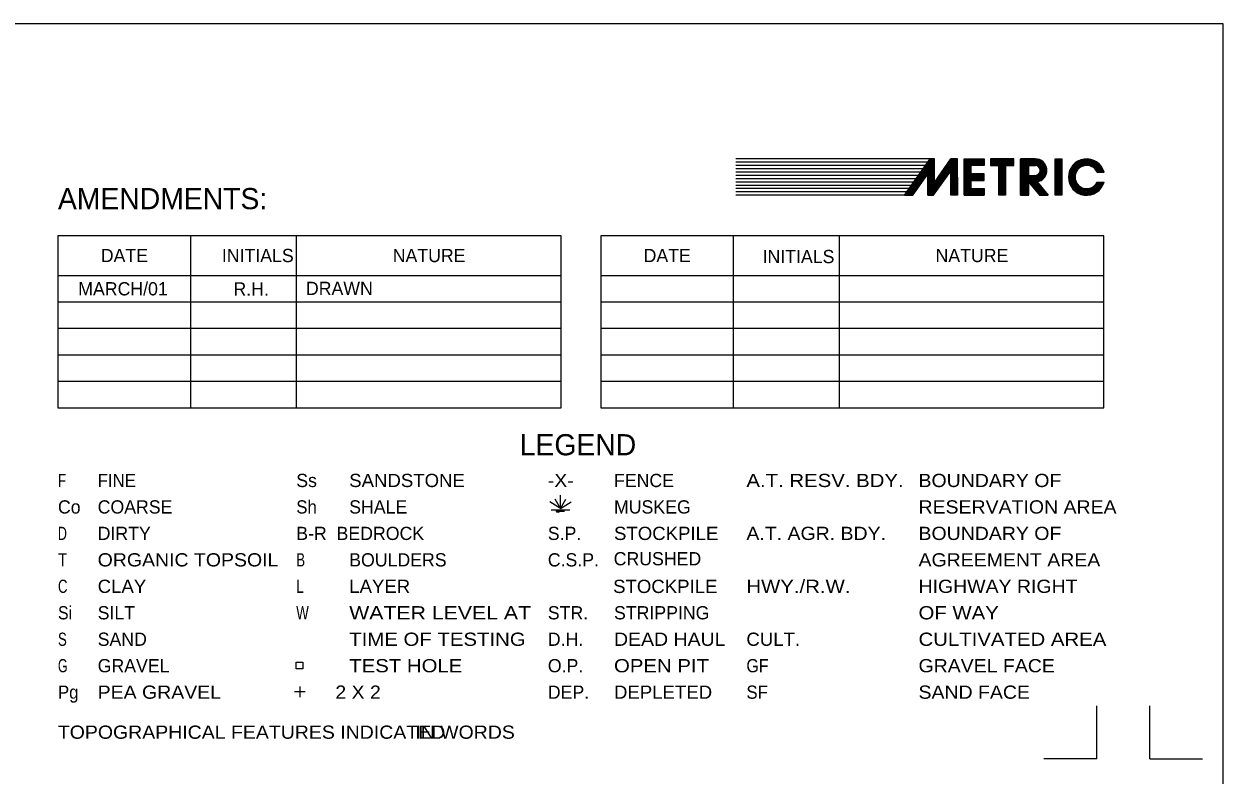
# Model space of a CAD drawing. Extents: x -496 to 480, y -452 to 700.
# Drawn here: x -2.8 to 450, y 416.2 to 700 of the extents above; entities that cross this region are included whole.
import ezdxf
from ezdxf.enums import TextEntityAlignment as Align

# ---------------------------------------------------------------- set-up
doc = ezdxf.new("R2010")
doc.units = 0
doc.header["$LTSCALE"] = 2
doc.header["$PDMODE"] = 32
doc.header["$PDSIZE"] = 1
doc.layers.add('3', color=7, linetype='Continuous', lineweight=13)

msp = doc.modelspace()

# ---------------------------------------------------------------- linework, layer by layer
at = {"layer": '3'}
for p, q in [((339.376, 648.989), (265.976, 648.989)), ((338.501, 647.739), (265.976, 647.739)), ((329.726, 635.239), (339.376, 648.989)), ((340.976, 640.064), (347.226, 648.989)), ((349.726, 648.989), (347.226, 648.989)), ((349.726, 635.239), (349.726, 648.989)), ((362.226, 648.989), (362.226, 646.489)), ((379.026, 648.989), (373.476, 648.989)), ((337.626, 646.489), (265.976, 646.489)), ((336.751, 645.239), (265.976, 645.239)), ((335.876, 643.989), (265.976, 643.989)), ((332.776, 635.239), (338.476, 643.364)), ((338.476, 635.239), (338.476, 643.389)), ((340.676, 635.264), (347.226, 644.614)), ((347.226, 635.239), (347.226, 644.614)), ((354.726, 646.489), (354.726, 643.364)), ((362.226, 646.489), (365.351, 646.489)), ((367.851, 646.489), (370.976, 646.489)), ((376.601, 646.489), (379.151, 646.489)), ((376.601, 642.739), (376.601, 646.489)), ((402.426, 643.989), (405.076, 643.989)), ((335.001, 642.739), (265.976, 642.739)), ((334.126, 641.489), (265.976, 641.489)), ((333.251, 640.239), (265.976, 640.239)), ((332.376, 638.989), (265.976, 638.989)), ((354.726, 640.864), (354.726, 637.739)), ((376.601, 642.739), (379.151, 642.739)), ((376.601, 640.239), (380.726, 635.239)), ((376.601, 635.239), (376.601, 640.239)), ((379.801, 640.289), (383.951, 635.239)), ((402.426, 640.239), (405.101, 640.239)), ((331.501, 637.739), (265.976, 637.739)), ((330.626, 636.489), (265.976, 636.489)), ((329.726, 635.239), (265.976, 635.239)), ((329.726, 635.239), (332.776, 635.239)), ((338.476, 635.239), (340.676, 635.239)), ((349.726, 635.239), (347.226, 635.239)), ((352.226, 635.239), (359.726, 635.239)), ((380.726, 635.239), (383.951, 635.239)), ((199.983, 619.973), (9.983, 619.973)), ((9.983, 619.973), (9.983, 554.973)), ((59.983, 619.973), (59.983, 554.973)), ((99.983, 619.973), (99.983, 554.973)), ((199.983, 554.973), (199.983, 619.973)), ((404.983, 619.973), (214.983, 619.973)), ((214.983, 619.973), (214.983, 554.973)), ((264.983, 619.973), (264.983, 554.973)), ((304.983, 619.973), (304.983, 554.973)), ((404.983, 554.973), (404.983, 619.973)), ((9.983, 604.973), (199.983, 604.973)), ((214.983, 604.973), (404.983, 604.973)), ((9.983, 594.973), (199.983, 594.973)), ((214.983, 594.973), (404.983, 594.973)), ((9.983, 584.973), (199.983, 584.973)), ((214.983, 584.973), (404.983, 584.973)), ((9.983, 574.973), (199.983, 574.973)), ((214.983, 574.973), (404.983, 574.973)), ((9.983, 564.973), (199.983, 564.973)), ((214.983, 564.973), (404.983, 564.973)), ((214.983, 554.973), (404.983, 554.973)), ((199.76, 516.875), (199.76, 521.875)), ((199.76, 516.875), (195.76, 519.375)), ((196.26, 516.375), (203.26, 516.375)), ((199.76, 516.875), (197.76, 520.375)), ((199.76, 516.875), (201.76, 520.375)), ((199.76, 516.875), (203.76, 519.375)), ((198.26, 515.875), (201.26, 515.875)), ((101.291, 449.597), (101.291, 445.597)), ((103.353, 447.618), (99.353, 447.618)), ((402.281, 422.339), (402.281, 442.339)), ((422.281, 422.339), (422.281, 442.339)), ((402.281, 422.339), (382.281, 422.339)), ((422.281, 422.339), (442.281, 422.339))]:
    msp.add_line(p, q, dxfattribs=at)
for points in [[(449.983, -450.027), (449.983, 399.973), (449.983, 699.973), (-450.017, 699.973), (-450.017, 49.973), (-450.017, -450.027)], [(329.901, 635.339), (339.401, 648.889), (340.901, 648.889), (340.901, 639.839), (347.251, 648.839), (349.626, 648.889), (349.676, 635.339), (347.351, 635.314), (347.301, 644.789), (340.576, 635.339), (338.576, 635.314), (338.576, 643.539), (332.701, 635.339), (330.076, 635.314), (339.501, 648.739), (340.801, 648.739), (340.776, 639.664), (347.276, 648.664), (349.526, 648.739), (349.651, 635.564), (347.501, 635.464), (347.426, 644.989), (340.526, 635.489), (338.726, 635.439), (338.676, 643.764), (332.651, 635.464), (330.301, 635.439), (339.576, 648.539), (340.651, 648.564), (340.651, 639.489), (347.351, 648.489), (349.301, 648.564), (349.476, 635.739), (347.726, 635.639), (347.626, 645.314), (340.451, 635.714), (338.926, 635.639), (338.876, 644.139), (332.501, 635.689), (330.701, 635.639)], [(330.701, 635.639), (339.651, 648.239), (340.326, 648.264), (340.476, 639.239), (347.526, 648.239), (349.126, 648.289), (349.226, 635.939), (348.001, 635.939), (347.851, 645.664), (340.326, 635.989), (339.151, 635.864), (339.126, 644.464), (332.401, 635.939), (331.076, 635.839), (339.651, 647.914), (340.151, 647.914), (340.251, 638.889), (347.601, 647.964), (348.926, 648.014), (349.026, 636.164), (348.251, 636.139), (348.051, 646.014), (340.226, 636.239), (339.351, 636.089), (339.326, 644.789), (332.226, 636.164), (331.476, 636.064), (339.701, 647.664), (339.926, 647.689), (340.126, 638.764), (347.751, 647.839), (348.701, 647.739), (348.826, 636.364), (348.476, 636.364), (348.176, 646.314), (340.126, 636.464), (339.551, 636.339), (339.426, 645.114), (332.201, 636.339), (331.851, 636.289)], [(331.851, 636.289), (339.701, 647.264), (339.926, 638.564), (347.826, 647.614), (348.451, 647.589), (348.701, 636.589), (348.251, 646.639), (340.126, 636.689), (339.726, 636.589), (339.576, 645.539), (332.301, 636.639), (339.526, 646.714), (339.576, 645.814), (335.101, 640.239), (339.401, 646.164), (339.401, 645.914), (338.176, 644.289)], [(340.976, 640.039), (340.976, 648.989), (339.376, 648.989)], [(352.226, 635.239), (352.226, 648.989), (359.726, 648.989)], [(352.376, 648.914), (359.651, 648.864), (359.676, 646.614), (354.626, 646.589), (354.626, 643.289), (359.651, 643.289), (359.651, 640.989), (354.651, 640.939), (354.626, 637.614), (359.676, 637.639), (359.651, 635.339), (352.351, 635.314), (352.376, 648.789), (359.551, 648.739), (359.551, 646.764), (354.501, 646.714), (354.501, 643.214), (359.551, 643.164), (359.551, 641.114), (354.551, 641.064), (354.526, 637.439), (359.551, 637.514), (359.501, 635.439), (352.501, 635.439), (352.576, 648.639), (359.401, 648.564), (359.426, 646.914), (354.376, 646.839), (354.351, 643.064), (359.426, 643.039), (359.376, 641.289), (354.401, 641.239), (354.376, 637.239), (359.401, 637.339), (359.376, 635.589), (352.701, 635.614), (352.726, 648.439), (359.226, 648.414), (359.251, 647.064), (354.251, 647.039)], [(354.251, 647.039), (354.176, 642.864), (359.251, 642.864), (359.176, 641.439), (354.251, 641.389), (354.201, 637.064), (359.201, 637.114), (359.176, 635.739), (352.926, 635.814), (352.976, 648.214), (359.026, 648.239), (359.076, 647.289), (354.076, 647.214), (354.001, 642.689), (359.051, 642.664), (359.026, 641.639), (354.076, 641.564), (354.026, 636.864), (359.051, 636.939), (359.026, 635.989), (353.126, 636.039), (353.226, 647.989), (358.801, 648.039), (358.826, 647.464), (353.926, 647.389), (353.851, 642.489), (358.876, 642.539), (358.801, 641.814), (353.951, 641.689), (353.851, 636.714), (358.901, 636.764), (358.901, 636.214), (353.351, 636.214), (353.476, 647.714), (358.601, 647.889), (358.626, 647.639), (353.776, 647.514), (353.751, 642.364), (358.626, 642.389), (358.601, 642.014)], [(358.601, 642.014), (353.826, 641.864), (353.726, 636.564), (358.701, 636.639), (358.701, 636.389), (353.551, 636.439), (353.626, 641.989), (358.376, 642.164), (358.326, 642.289), (353.576, 642.264), (353.676, 647.564)], [(359.726, 648.989), (359.726, 646.489), (354.726, 646.489)], [(370.976, 646.489), (370.976, 648.989), (362.226, 648.989)], [(362.351, 648.864), (370.851, 648.889), (370.851, 646.639), (367.701, 646.639), (367.751, 635.414), (365.451, 635.314), (365.451, 646.564), (362.351, 646.589), (362.351, 648.764), (370.801, 648.789), (370.726, 646.789), (367.601, 646.764), (367.676, 635.539), (365.576, 635.414), (365.626, 646.739), (362.476, 646.739), (362.476, 648.639), (370.626, 648.639), (370.576, 646.989), (367.426, 646.864), (367.526, 635.739), (365.751, 635.614), (365.776, 646.864), (362.701, 646.939), (362.726, 648.439), (370.451, 648.489), (370.376, 647.114), (367.276, 646.989), (367.376, 635.914), (365.901, 635.789), (365.951, 647.064), (362.901, 647.114), (362.901, 648.264), (370.201, 648.289), (370.201, 647.364), (367.076, 647.189), (367.226, 636.114), (366.126, 635.989), (366.101, 647.264), (363.101, 647.314)], [(363.101, 647.314), (363.151, 648.089), (369.976, 648.164), (369.926, 647.489), (366.876, 647.364), (367.026, 636.339), (366.351, 636.239), (366.276, 647.439), (363.326, 647.514), (363.401, 647.939), (369.751, 648.039), (369.701, 647.714), (366.726, 647.539), (366.851, 636.564), (366.476, 636.489), (366.426, 647.664), (363.701, 647.664), (363.751, 647.839), (369.451, 647.914), (369.426, 647.814), (366.601, 647.664), (366.626, 636.689)], [(373.476, 648.989), (373.476, 635.239), (376.601, 635.239)], [(373.601, 648.914), (378.976, 648.889), (380.101, 648.739), (381.101, 648.364), (381.826, 647.789), (382.451, 647.189), (382.901, 646.414), (383.301, 645.389), (383.301, 644.439), (383.126, 643.214), (382.651, 642.314), (381.926, 641.489), (381.051, 640.889), (380.401, 640.639), (379.651, 640.389), (380.026, 639.714), (380.576, 639.189), (383.701, 635.339), (380.801, 635.314), (376.501, 640.464), (376.526, 635.339), (373.551, 635.314), (373.551, 648.864), (379.026, 648.789), (380.076, 648.639), (380.926, 648.314), (382.276, 647.214), (383.151, 645.364), (383.026, 643.314), (382.601, 642.464), (381.901, 641.614), (381.051, 640.989), (379.576, 640.464), (383.501, 635.414), (380.951, 635.439), (376.351, 640.739), (376.401, 635.489), (373.701, 635.439), (373.701, 648.739), (379.151, 648.664), (380.076, 648.489), (380.851, 648.189), (382.126, 647.139), (383.026, 645.389), (382.951, 643.539), (382.501, 642.564), (381.901, 641.739), (381.051, 641.114), (379.401, 640.614), (383.201, 635.564), (381.001, 635.564), (376.226, 640.889), (376.276, 635.614), (373.826, 635.539), (373.826, 648.614), (379.126, 648.489), (380.676, 648.089), (382.026, 647.139), (382.876, 645.439), (382.801, 643.664), (382.401, 642.664), (381.801, 641.889), (380.951, 641.189), (379.226, 640.764), (382.901, 635.689), (381.101, 635.689), (376.051, 641.064), (376.126, 635.789), (373.976, 635.689), (373.976, 648.439), (379.101, 648.364), (380.551, 647.989), (381.851, 647.089), (382.776, 645.439), (382.701, 643.764), (382.326, 642.889), (381.726, 642.064), (380.901, 641.339), (379.026, 640.939), (382.601, 635.789), (381.126, 635.814), (375.876, 641.239), (375.976, 635.939), (374.126, 635.864), (374.126, 648.239), (379.026, 648.239), (380.251, 647.914), (381.676, 647.014), (382.576, 645.414), (382.601, 643.914), (382.276, 642.989), (381.651, 642.214), (380.826, 641.514), (378.851, 641.064), (382.351, 635.939), (381.176, 635.989), (375.776, 641.514), (375.826, 636.089), (374.251, 636.014), (374.276, 648.039), (378.976, 648.114)], [(378.976, 648.114), (379.026, 648.114), (380.201, 647.764), (381.526, 646.939), (382.401, 645.489), (382.401, 643.964), (382.076, 643.114), (380.826, 641.764), (378.601, 641.264), (382.001, 636.114), (381.351, 636.114), (375.676, 641.789), (375.676, 636.264), (374.376, 636.189), (374.451, 647.864), (378.926, 647.939), (380.176, 647.689), (381.351, 646.914), (382.151, 645.414), (382.201, 644.014), (381.901, 643.214), (380.726, 641.989), (378.401, 641.389), (381.676, 636.314), (381.501, 636.189), (375.526, 642.064), (375.476, 636.414), (374.551, 636.339), (374.651, 647.739), (379.976, 647.614), (381.151, 646.914), (382.001, 645.414), (382.051, 644.139), (381.726, 643.339), (380.651, 642.139), (378.226, 641.589), (381.401, 636.464), (375.401, 642.364), (375.376, 636.614), (374.676, 636.539), (374.901, 647.589), (379.826, 647.414), (380.851, 646.889), (381.801, 645.439), (381.901, 644.389), (381.576, 643.539), (380.576, 642.414), (378.051, 641.739), (380.676, 637.364), (375.376, 642.614), (375.226, 636.739), (374.851, 636.739), (375.076, 647.339), (379.601, 647.314), (380.676, 646.839), (381.626, 645.414), (381.726, 644.464), (381.376, 643.589), (380.501, 642.589), (377.826, 641.864), (380.026, 638.189), (375.251, 642.889), (375.076, 636.939), (374.926, 636.989), (375.226, 647.189), (379.526, 647.139), (380.551, 646.714), (381.401, 645.414), (381.551, 644.614), (380.376, 642.739), (377.726, 642.039), (379.276, 639.239), (375.351, 643.039), (375.426, 646.989), (379.476, 646.989), (380.526, 646.639), (381.251, 645.489), (381.326, 644.614), (380.276, 642.914), (377.551, 642.239), (378.601, 640.139), (375.576, 643.139), (375.676, 646.839), (379.451, 646.839), (380.476, 646.514), (381.101, 645.414), (381.051, 644.489), (380.876, 645.464), (380.501, 646.039), (380.151, 646.339), (379.476, 646.514), (378.751, 646.639), (377.601, 646.614), (376.476, 646.614), (376.501, 642.714), (378.626, 642.664), (377.376, 642.339), (378.126, 640.764), (375.726, 643.164), (375.876, 646.714), (379.451, 646.714)], [(386.776, 648.839), (388.951, 648.864), (389.001, 635.364), (386.701, 635.364), (386.676, 648.739), (388.851, 648.764), (388.876, 635.489), (386.826, 635.439), (386.801, 648.614), (388.776, 648.639), (388.776, 635.664), (386.976, 635.589), (386.926, 648.464), (388.626, 648.464), (388.601, 635.764), (387.126, 635.764), (387.101, 648.364), (388.501, 648.364), (388.451, 635.939), (387.301, 635.964), (387.301, 648.214), (388.401, 648.214), (388.301, 636.089), (387.426, 636.089), (387.476, 648.064), (388.251, 648.039), (388.151, 636.214), (387.576, 636.214), (387.676, 647.914), (388.126, 647.889), (388.001, 636.339), (387.776, 636.389), (387.826, 647.764), (387.976, 647.714), (387.901, 636.539)], [(404.901, 644.089), (404.451, 645.189), (403.851, 646.164), (403.151, 646.914), (402.301, 647.639), (401.151, 648.289), (400.126, 648.614), (398.801, 648.814), (397.351, 648.689), (395.876, 648.339), (394.601, 647.639), (393.601, 646.764), (392.776, 645.664), (392.176, 644.564), (391.801, 642.964), (391.801, 641.264), (392.176, 639.789), (392.726, 638.564), (393.351, 637.739), (394.101, 637.014), (394.976, 636.389), (395.901, 635.914), (397.126, 635.489), (398.726, 635.389), (400.151, 635.589), (401.301, 635.989), (402.326, 636.564), (403.326, 637.414), (404.001, 638.264), (404.426, 639.139), (404.801, 640.064), (402.526, 640.089), (401.776, 638.989), (400.776, 638.289), (399.801, 637.814), (398.476, 637.564), (397.026, 637.839), (396.126, 638.289), (395.276, 638.939), (394.551, 639.939), (394.076, 641.189), (394.051, 642.814), (394.276, 643.889), (394.901, 644.889), (395.601, 645.614), (396.476, 646.164), (397.376, 646.489), (398.426, 646.614), (399.526, 646.489), (400.426, 646.214), (401.176, 645.764), (401.801, 645.239), (402.301, 644.664), (402.576, 644.139), (404.726, 644.164), (404.251, 645.214), (403.651, 646.164), (402.276, 647.489), (401.126, 648.114), (399.351, 648.614), (397.876, 648.564), (396.551, 648.339), (395.226, 647.814), (394.351, 647.264), (393.451, 646.339), (392.676, 645.139), (392.176, 643.939), (391.976, 642.239), (392.076, 640.689), (392.576, 639.164), (393.476, 637.864), (394.526, 636.864), (395.701, 636.164), (397.201, 635.639), (398.626, 635.514), (400.251, 635.764), (401.276, 636.089), (402.301, 636.789), (403.176, 637.439), (403.726, 638.164), (404.376, 639.239), (404.551, 639.964), (402.626, 639.989), (402.076, 639.064), (400.751, 638.139), (399.826, 637.689), (398.526, 637.389), (396.976, 637.739), (395.601, 638.439), (394.651, 639.639), (394.076, 640.764), (393.876, 642.139), (394.151, 643.989), (394.726, 644.964), (395.826, 646.014), (397.051, 646.539), (398.351, 646.789), (399.826, 646.614), (401.026, 646.064), (401.701, 645.614), (402.226, 645.014)], [(402.226, 645.014), (402.301, 645.014), (402.676, 644.239), (404.476, 644.264), (404.026, 645.314), (402.876, 646.664), (401.901, 647.489), (400.851, 648.089), (399.251, 648.514), (396.976, 648.264), (395.201, 647.614), (394.051, 646.639), (393.151, 645.614), (392.526, 644.239), (392.176, 642.439), (392.326, 640.539), (392.676, 639.489), (392.951, 638.864), (393.701, 637.864), (394.851, 636.839), (397.101, 635.814), (398.651, 635.664), (401.026, 636.164), (403.076, 637.564), (403.901, 638.814), (404.326, 639.814), (403.476, 639.789), (402.726, 639.839), (402.201, 638.889), (400.776, 637.964), (399.526, 637.414), (398.251, 637.264), (396.651, 637.714), (395.476, 638.364), (394.451, 639.714), (393.901, 640.864), (393.701, 642.264), (393.976, 643.889), (394.651, 645.264), (395.701, 646.214), (397.376, 646.789), (398.851, 646.914), (400.251, 646.614), (401.626, 645.914), (402.426, 645.164), (402.801, 644.439), (404.226, 644.414), (403.426, 645.739), (402.676, 646.614), (401.826, 647.314), (400.851, 647.939), (399.276, 648.314), (397.051, 648.089), (395.226, 647.364), (393.976, 646.314), (393.201, 645.414), (392.651, 643.839), (392.426, 642.514), (392.451, 641.239), (392.651, 640.089), (393.101, 639.039), (393.651, 638.239), (394.376, 637.564), (395.226, 636.839), (396.351, 636.314), (397.451, 635.914), (398.701, 635.839), (400.826, 636.364), (402.976, 637.639), (403.801, 638.964), (404.026, 639.714), (402.851, 639.664), (402.326, 638.814), (401.226, 638.164), (399.651, 637.239), (398.226, 637.114), (397.101, 637.389), (395.976, 637.889), (394.801, 638.989), (394.101, 640.014), (393.601, 641.664), (393.676, 643.264), (394.101, 644.689), (395.376, 646.214), (396.876, 646.764), (398.751, 647.064), (400.326, 646.764), (401.751, 646.089), (402.651, 645.189), (402.951, 644.539), (403.876, 644.614), (403.051, 645.989), (402.201, 646.789), (400.851, 647.739), (399.376, 648.189), (397.151, 647.889), (395.451, 647.239), (394.076, 646.164), (393.251, 645.039), (392.701, 643.014), (392.651, 641.564)], [(392.651, 641.564), (392.676, 641.614), (392.951, 639.914), (393.451, 638.964), (394.051, 638.214), (394.926, 637.289), (395.951, 636.764), (396.601, 636.389), (397.801, 636.039), (398.776, 635.989), (400.726, 636.464), (402.951, 637.739), (403.651, 639.064), (403.726, 639.564), (403.026, 639.539), (402.576, 638.814), (399.876, 637.114), (398.026, 637.014), (396.051, 637.664), (394.476, 639.139), (393.526, 641.439), (393.651, 643.889), (394.476, 645.514), (395.726, 646.539), (397.351, 646.989), (398.701, 647.239), (400.476, 646.939), (401.751, 646.339), (402.526, 645.664), (402.851, 645.114), (403.076, 644.739), (403.551, 644.789), (402.926, 645.989), (401.801, 646.914), (400.676, 647.639), (399.376, 648.039), (397.176, 647.789), (395.676, 647.164), (394.226, 646.139), (393.501, 645.039), (392.901, 643.314), (392.826, 641.639), (393.126, 639.989), (393.851, 638.689), (394.951, 637.514), (396.001, 636.989), (396.726, 636.564), (398.626, 636.139), (400.701, 636.614), (402.776, 637.864), (403.476, 639.064), (403.601, 639.464), (403.251, 639.389), (402.751, 638.739), (400.001, 637.014), (398.001, 636.889), (395.901, 637.564), (394.326, 639.064), (393.376, 641.464), (393.576, 643.939), (394.301, 645.589), (395.526, 646.689), (398.576, 647.339), (400.751, 647.089), (401.751, 646.489), (402.601, 645.914), (403.076, 645.039), (403.326, 644.914), (402.851, 645.939), (400.926, 647.289), (399.526, 647.889), (397.401, 647.714), (395.626, 647.039), (394.251, 646.039), (393.576, 644.889), (393.026, 643.239), (392.951, 641.714), (393.276, 640.314), (393.801, 639.139), (394.376, 638.339), (395.076, 637.639), (396.901, 636.764), (398.651, 636.314), (400.576, 636.789), (402.601, 637.914), (403.351, 639.139), (402.501, 638.339), (401.601, 637.789), (400.101, 636.864), (398.051, 636.764), (395.801, 637.439), (394.176, 639.064), (393.226, 641.539), (393.501, 644.014), (394.126, 645.639), (395.451, 646.739), (397.026, 647.189), (398.576, 647.489), (399.776, 647.389), (400.526, 647.289), (399.551, 647.639)], [(399.551, 647.639), (398.601, 647.639), (397.451, 647.489), (395.901, 647.064)], [(339.901, 638.414), (339.926, 636.839), (348.276, 646.889), (348.326, 647.439), (347.951, 647.439), (340.126, 638.539), (340.151, 637.314), (348.176, 647.064), (348.051, 647.214), (340.326, 638.539), (340.401, 637.839), (347.851, 646.839), (340.501, 638.639), (340.526, 638.389), (344.426, 642.914)], [(354.726, 640.864), (359.726, 640.864), (359.726, 643.364), (354.726, 643.364)], [(367.851, 646.489), (367.851, 635.239), (365.351, 635.239), (365.351, 646.489)], [(376.026, 646.614), (375.901, 643.214), (377.551, 641.614), (377.251, 642.364), (377.776, 642.614), (376.826, 642.614), (377.201, 642.164)], [(376.151, 646.564), (376.051, 643.314), (376.376, 643.064), (376.351, 646.564), (376.251, 643.389)], [(379.451, 646.714), (379.401, 646.739), (380.451, 646.289)], [(402.751, 638.439), (402.076, 637.814), (400.676, 637.089), (399.226, 636.639), (398.501, 636.639), (396.951, 636.914), (395.751, 637.364), (394.201, 638.764), (393.101, 641.589), (393.401, 643.964), (393.901, 645.289)], [(354.726, 637.739), (359.726, 637.739), (359.726, 635.239)], [(9.983, 554.973), (99.983, 554.973), (199.983, 554.973)]]:
    msp.add_lwpolyline(points, dxfattribs=at)
for points in [[(386.601, 635.239), (386.601, 648.989), (389.101, 648.989), (389.101, 635.239)], [(99.967, 456.301), (99.967, 458.832), (102.499, 458.832), (102.499, 456.301)]]:
    msp.add_lwpolyline(points, close=True, dxfattribs=at)
for centre, radius, start, end in [((379.076, 644.614), 4.375, 279.51602, 90.65478), ((398.476, 642.114), 6.875, 15.80251, 344.19749), ((379.051, 644.614), 1.875, 272.29061, 86.94712), ((398.476, 642.114), 4.375, 25.39292, 334.60708)]:
    msp.add_arc(centre, radius, start, end, dxfattribs=at)
msp.add_point((198.76, 515.875), dxfattribs=at)

# ---------------------------------------------------------------- texts
for s, height, p in [('AMENDMENTS:', 8, (9.983, 629.973)), ('Ss', 5, (99.983, 524.973)), ('FENCE', 5, (219.983, 524.973)), ('Co', 5, (9.983, 514.973)), ('COARSE', 5, (24.983, 514.973)), ('SHALE', 5, (119.983, 514.973)), ('MUSKEG', 5, (219.983, 514.973)), ('DIRTY', 5, (24.983, 504.973)), ('B-R  BEDROCK', 5, (99.983, 504.973)), ('S.P.', 5, (194.983, 504.973)), ('BOULDERS', 5, (119.983, 494.973)), ('C.S.P.', 5, (194.983, 494.973)), ('CRUSHED', 5, (219.856, 495.402)), ('SILT', 5, (24.983, 474.973)), ('STR.', 5, (194.983, 474.973)), ('STRIPPING', 5, (219.983, 474.973)), ('SAND', 5, (24.983, 464.973)), ('D.H.', 5, (194.983, 464.973)), ('GRAVEL', 5, (24.983, 454.973)), ('O.P.', 5, (194.983, 454.973)), ('DEP.', 5, (194.983, 444.973))]:
    msp.add_text(s, height=height, dxfattribs=at).set_placement(p)
for s, height, p in [('DATE', 5, (35.081, 609.973)), ('INITIALS', 5, (85.453, 609.973)), ('NATURE', 5, (150.16, 609.973)), ('DATE', 5, (240.081, 609.973)), ('INITIALS', 5, (289.66, 609.584)), ('NATURE', 5, (355.16, 609.973)), ('MARCH/01', 5, (34.552, 597.405)), ('R.H.', 5, (82.941, 597.343)), ('DRAWN', 5, (116.266, 597.567)), ('LEGEND', 8, (206.378, 536.973))]:
    msp.add_text(s, height=height, dxfattribs=at).set_placement(p, align=Align.CENTER)
for s, width, p in [('F', 0.75, (9.983, 524.973)), ('FINE', 0.95, (24.983, 524.973)), ('SANDSTONE', 1.05, (119.983, 524.973)), ('-X-', 1.1, (194.983, 524.973)), ('A.T. RESV. BDY.', 1.15, (269.983, 524.973)), ('BOUNDARY OF', 1.1, (334.983, 524.973)), ('Sh', 0.95, (99.983, 514.973)), ('RESERVATION AREA', 1.1, (334.983, 514.973)), ('D', 0.7, (9.983, 504.973)), ('STOCKPILE', 1.05, (219.983, 504.973)), ('A.T. AGR. BDY.', 1.1, (269.983, 504.973)), ('BOUNDARY OF', 1.1, (334.983, 504.973)), ('T', 0.85, (9.983, 494.973)), ('ORGANIC TOPSOIL', 1.1, (24.983, 494.973)), ('B', 0.75, (99.983, 494.973)), ('AGREEMENT AREA', 1.1, (334.983, 494.973)), ('C', 0.75, (9.983, 484.973)), ('CLAY', 1.05, (24.983, 484.973)), ('L', 0.75, (99.983, 484.973)), ('LAYER', 1.05, (119.983, 484.973)), ('STOCKPILE', 1.05, (219.649, 484.941)), ('HWY./R.W.', 1.15, (269.983, 484.973)), ('HIGHWAY RIGHT', 1.1, (334.983, 484.973)), ('Si', 0.9, (9.983, 474.973)), ('OF WAY', 1.15, (334.983, 474.973)), ('W', 0.75, (99.983, 474.973)), ('WATER LEVEL AT', 1.2, (119.983, 474.973)), ('S', 0.75, (9.983, 464.973)), ('TIME OF TESTING', 1.15, (119.983, 464.973)), ('DEAD HAUL', 1.1, (219.983, 464.973)), ('CULT.', 1.05, (269.983, 464.973)), ('CULTIVATED AREA', 1.15, (334.983, 464.973)), ('G', 0.7, (9.983, 454.973)), ('TEST HOLE', 1.15, (119.983, 454.973)), ('OPEN PIT', 1.15, (219.983, 454.973)), ('GF', 0.9, (269.983, 454.973)), ('GRAVEL FACE', 1.1, (334.983, 454.973)), ('Pg', 0.95, (9.983, 444.973)), ('PEA GRAVEL', 1.1, (24.983, 444.973)), ('   2 X 2', 1.1, (108.608, 444.973)), ('DEPLETED', 1.05, (219.983, 444.973)), ('SF', 0.95, (269.983, 444.973)), ('SAND FACE', 1.1, (334.983, 444.973)), ('TOPOGRAPHICAL FEATURES INDICATED', 1.1, (9.942, 429.855)), ('IN WORDS', 1.1, (144.942, 429.855))]:
    msp.add_text(s, height=5, dxfattribs=dict(at, width=width)).set_placement(p)

doc.saveas('drawing.dxf')
